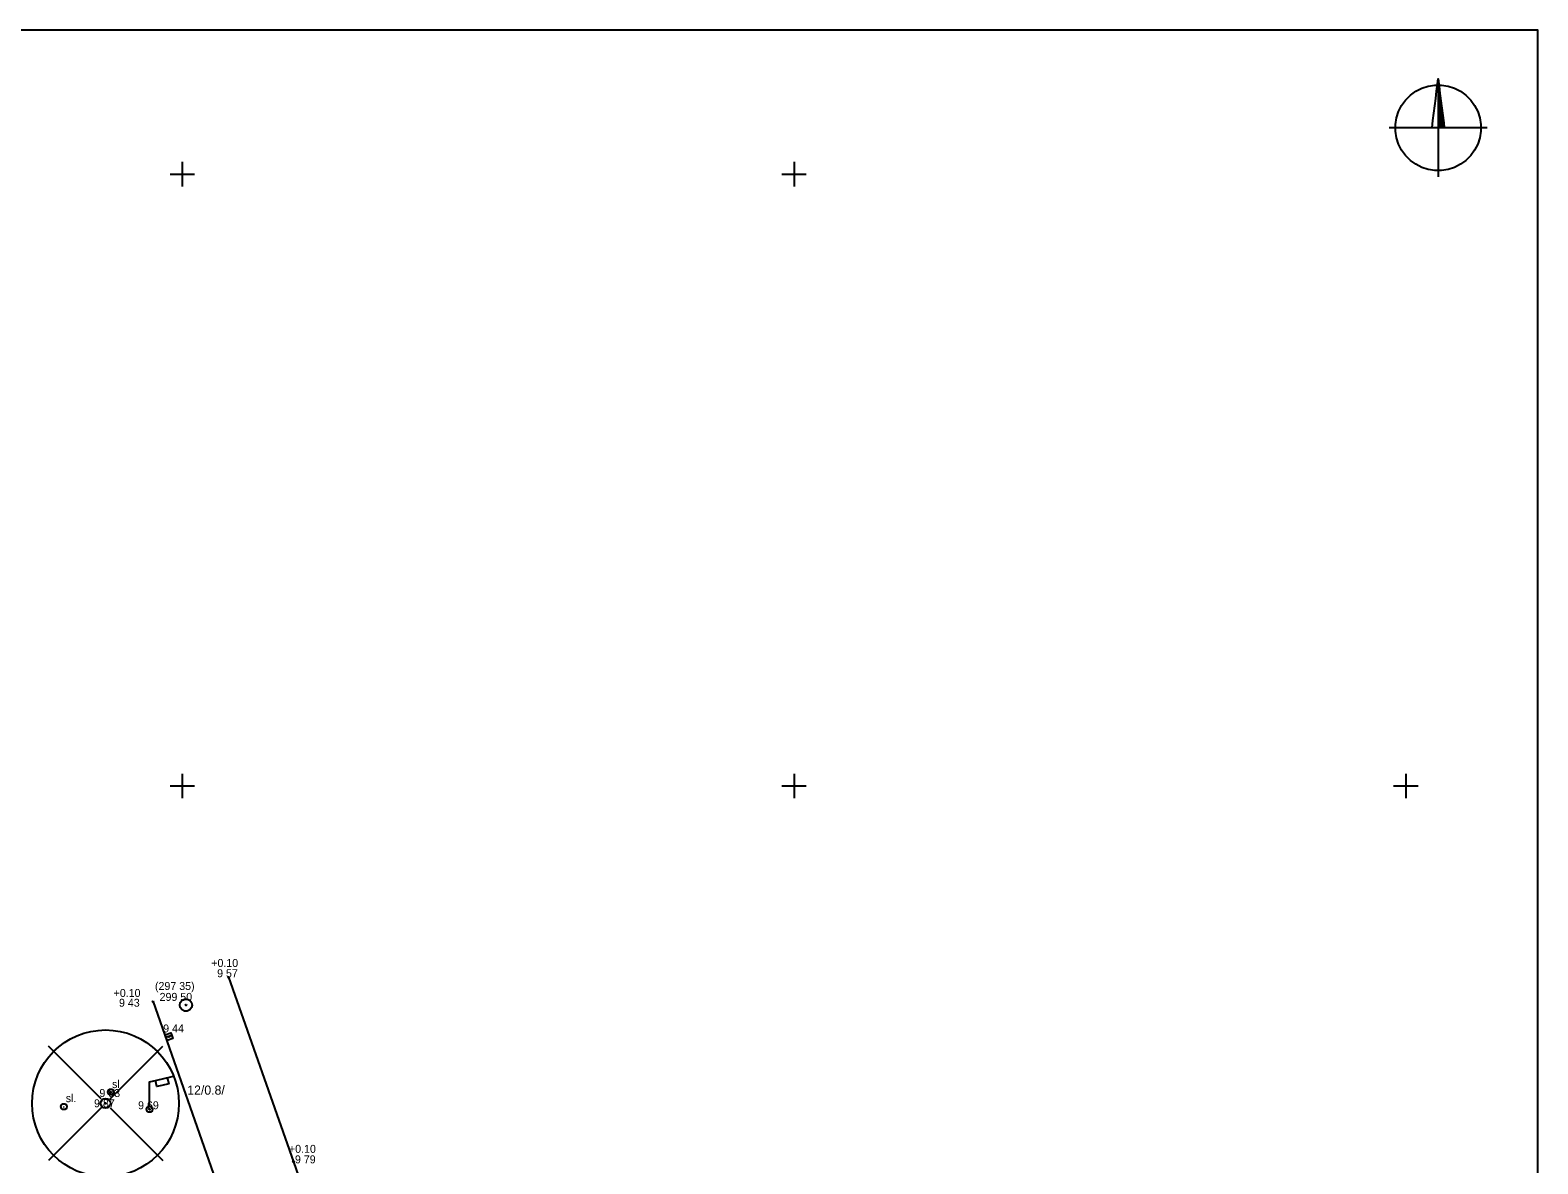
# Model space of a CAD drawing. Extents: x -684336 to -684039, y -993109 to -992688.
# Drawn here: x -684162.4 to -684039.2, y -992780.9 to -992688.2 of the extents above; entities that cross this region are included whole.
import ezdxf

# ---------------------------------------------------------------- set-up
doc = ezdxf.new("R2010")
doc.units = 0
for name, color, linetype in [('51', 7, 'Continuous'), ('53', 7, 'Continuous'), ('55', 7, 'Continuous'), ('56', 7, 'Continuous'), ('57', 7, 'Continuous'), ('60', 7, 'Continuous')]:
    doc.layers.add(name, color=color, linetype=linetype)

msp = doc.modelspace()

# ---------------------------------------------------------------- linework, layer by layer
at = {"layer": '51'}
for points in [[(-684146.21, -992765.63), (-684140.91, -992780.71), (-684133.67, -992801.48), (-684127.41, -992819.38), (-684119.65, -992841.73), (-684114.27, -992857.16), (-684108.6, -992873.5), (-684101.11, -992894.94), (-684096.5, -992908.14), (-684094.17, -992914.77), (-684093.17, -992916.04), (-684091.3, -992916.97), (-684089.29, -992917.17), (-684087.35, -992916.85), (-684086.32, -992916.52), (-684078.35, -992912.36)], [(-684152.39, -992767.63), (-684146.89, -992783.27), (-684139.8, -992803.58), (-684132.92, -992823.35), (-684125.99, -992843.22), (-684120.41, -992859.24), (-684115.07, -992874.61), (-684107.12, -992897.43), (-684102.52, -992910.64)]]:
    msp.add_lwpolyline(points, dxfattribs=at)
at = {"layer": '53'}
for points in [[(-684336.21, -993108.73), (-684039.21, -993108.73), (-684039.21, -992688.23), (-684336.21, -992688.23)], [(-684047.09, -992692.72), (-684046.55, -992692.8), (-684046.03, -992692.97), (-684045.54, -992693.22), (-684045.09, -992693.55), (-684044.7, -992693.94), (-684044.38, -992694.38), (-684044.13, -992694.87), (-684043.96, -992695.39), (-684043.87, -992695.93), (-684043.87, -992696.48), (-684043.96, -992697.02), (-684044.13, -992697.54), (-684044.38, -992698.03), (-684044.7, -992698.48), (-684045.09, -992698.87), (-684045.54, -992699.19), (-684046.03, -992699.44), (-684046.55, -992699.61), (-684047.09, -992699.7), (-684047.64, -992699.7), (-684048.18, -992699.61), (-684048.7, -992699.44), (-684049.19, -992699.19), (-684049.63, -992698.87), (-684050.02, -992698.48), (-684050.35, -992698.03), (-684050.6, -992697.54), (-684050.77, -992697.02), (-684050.85, -992696.48), (-684050.85, -992695.93), (-684050.77, -992695.39), (-684050.6, -992694.87), (-684050.35, -992694.38), (-684050.02, -992693.94), (-684049.63, -992693.55), (-684049.19, -992693.22), (-684048.7, -992692.97), (-684048.18, -992692.8), (-684047.64, -992692.72)]]:
    msp.add_lwpolyline(points, close=True, dxfattribs=at)
for points in [[(-684047.86, -992696.21), (-684047.79, -992695.61), (-684047.71, -992695.01), (-684047.64, -992694.41), (-684047.56, -992693.81), (-684047.49, -992693.21), (-684047.41, -992692.61), (-684047.36, -992692.21), (-684047.29, -992692.81), (-684047.21, -992693.41), (-684047.14, -992694.01), (-684047.06, -992694.61), (-684046.99, -992695.21), (-684046.91, -992695.81), (-684046.86, -992696.21), (-684046.9, -992696.17), (-684046.9, -992695.93), (-684046.94, -992695.61), (-684046.94, -992696.17), (-684046.98, -992696.17), (-684046.98, -992695.53), (-684046.98, -992695.29), (-684047.02, -992694.97), (-684047.02, -992695.6), (-684047.02, -992696.17), (-684047.06, -992696.17), (-684047.06, -992695.53), (-684047.06, -992694.9), (-684047.06, -992694.65), (-684047.1, -992694.37), (-684047.1, -992695), (-684047.1, -992695.64), (-684047.1, -992696.17), (-684047.14, -992696.17), (-684047.14, -992695.53), (-684047.14, -992694.9), (-684047.14, -992694.26), (-684047.14, -992694.05), (-684047.18, -992693.69), (-684047.18, -992694.32), (-684047.18, -992694.96), (-684047.18, -992695.59), (-684047.18, -992696.17), (-684047.22, -992696.17), (-684047.22, -992695.53), (-684047.22, -992694.9), (-684047.22, -992694.26), (-684047.22, -992693.63), (-684047.22, -992693.41), (-684047.26, -992693.05), (-684047.26, -992693.68), (-684047.26, -992694.32), (-684047.26, -992694.95), (-684047.26, -992695.59), (-684047.26, -992696.17), (-684047.3, -992696.17), (-684047.3, -992695.53), (-684047.3, -992694.9), (-684047.3, -992694.26), (-684047.3, -992693.63), (-684047.3, -992692.99), (-684047.3, -992692.73), (-684047.34, -992692.41), (-684047.34, -992693.04), (-684047.34, -992693.68), (-684047.34, -992694.31), (-684047.34, -992694.95), (-684047.34, -992695.58), (-684047.34, -992696.17)], [(-684047.36, -992692.21), (-684047.36, -992692.84), (-684047.36, -992693.48), (-684047.36, -992694.11), (-684047.36, -992694.75), (-684047.36, -992695.38), (-684047.36, -992696.02), (-684047.36, -992696.65), (-684047.36, -992697.29), (-684047.36, -992697.92), (-684047.36, -992698.56), (-684047.36, -992699.19), (-684047.36, -992699.83), (-684047.36, -992700.21)], [(-684043.36, -992696.21), (-684044, -992696.21), (-684044.63, -992696.21), (-684045.27, -992696.21), (-684045.9, -992696.21), (-684046.54, -992696.21), (-684047.17, -992696.21), (-684047.81, -992696.21), (-684048.44, -992696.21), (-684049.08, -992696.21), (-684049.71, -992696.21), (-684050.35, -992696.21), (-684050.98, -992696.21), (-684051.36, -992696.21)], [(-684150, -992699), (-684150, -992701)], [(-684100, -992699), (-684100, -992701)], [(-684151, -992700), (-684149, -992700)], [(-684101, -992700), (-684099, -992700)], [(-684150, -992749), (-684150, -992751)], [(-684100, -992749), (-684100, -992751)], [(-684050, -992749), (-684050, -992751)], [(-684151, -992750), (-684149, -992750)], [(-684101, -992750), (-684099, -992750)], [(-684051, -992750), (-684049, -992750)]]:
    msp.add_lwpolyline(points, dxfattribs=at)
at = {"layer": '55'}
for points in [[(-684149.59, -992767.42), (-684149.39, -992767.51), (-684149.25, -992767.69), (-684149.2, -992767.9), (-684149.25, -992768.11), (-684149.39, -992768.29), (-684149.59, -992768.39), (-684149.82, -992768.39), (-684150.01, -992768.29), (-684150.16, -992768.11), (-684150.2, -992767.9), (-684150.16, -992767.69), (-684150.01, -992767.51), (-684149.82, -992767.42)], [(-684155.75, -992774.78), (-684155.62, -992774.87), (-684155.58, -992775.02), (-684155.62, -992775.16), (-684155.75, -992775.25), (-684155.91, -992775.25), (-684156.03, -992775.16), (-684156.08, -992775.02), (-684156.03, -992774.87), (-684155.91, -992774.78)], [(-684159.59, -992775.97), (-684159.47, -992776.06), (-684159.42, -992776.2), (-684159.47, -992776.35), (-684159.59, -992776.44), (-684159.75, -992776.44), (-684159.87, -992776.35), (-684159.92, -992776.2), (-684159.87, -992776.06), (-684159.75, -992775.97)]]:
    msp.add_lwpolyline(points, close=True, dxfattribs=at)
for points in [[(-684150.85, -992770.4), (-684150.77, -992770.63), (-684151.24, -992770.8), (-684151.41, -992770.33), (-684150.94, -992770.16), (-684150.85, -992770.4), (-684151.33, -992770.56)], [(-684152.67, -992776.19), (-684152.59, -992776.19), (-684152.47, -992776.28), (-684152.42, -992776.42), (-684152.47, -992776.57), (-684152.59, -992776.66), (-684152.75, -992776.66), (-684152.87, -992776.57), (-684152.92, -992776.42), (-684152.87, -992776.28), (-684152.75, -992776.19), (-684152.67, -992776.19), (-684152.67, -992775.55), (-684152.67, -992774.92), (-684152.67, -992774.28), (-684152.67, -992774.17), (-684152.08, -992774.04), (-684151.5, -992773.9), (-684150.92, -992773.77), (-684150.72, -992773.72)], [(-684151.22, -992773.84), (-684151.09, -992774.34), (-684151.68, -992774.48), (-684152.07, -992774.57), (-684152.2, -992774.07)], [(-684155.85, -992775.02), (-684155.8, -992775.02)], [(-684159.7, -992776.21), (-684159.64, -992776.21)], [(-684152.7, -992776.42), (-684152.65, -992776.42)]]:
    msp.add_lwpolyline(points, dxfattribs=at)
at = {"layer": '57'}
for points in [[(-684146.19, -992765.59), (-684146.16, -992765.63), (-684146.19, -992765.67), (-684146.23, -992765.67), (-684146.26, -992765.63), (-684146.23, -992765.59)], [(-684152.37, -992767.59), (-684152.34, -992767.63), (-684152.37, -992767.67), (-684152.41, -992767.67), (-684152.44, -992767.63), (-684152.41, -992767.59)], [(-684149.68, -992767.86), (-684149.65, -992767.9), (-684149.68, -992767.94), (-684149.72, -992767.94), (-684149.74, -992767.9), (-684149.72, -992767.86)], [(-684151.07, -992770.44), (-684151.04, -992770.48), (-684151.07, -992770.52), (-684151.11, -992770.52), (-684151.14, -992770.48), (-684151.11, -992770.44)], [(-684155.81, -992774.98), (-684155.78, -992775.02), (-684155.81, -992775.06), (-684155.85, -992775.06), (-684155.88, -992775.02), (-684155.85, -992774.98)], [(-684156.25, -992775.9), (-684156.22, -992775.94), (-684156.25, -992775.98), (-684156.29, -992775.98), (-684156.32, -992775.94), (-684156.29, -992775.9)], [(-684152.65, -992776.38), (-684152.62, -992776.42), (-684152.65, -992776.46), (-684152.69, -992776.46), (-684152.72, -992776.42), (-684152.69, -992776.38)], [(-684140.89, -992780.67), (-684140.86, -992780.71), (-684140.89, -992780.75), (-684140.93, -992780.75), (-684140.96, -992780.71), (-684140.93, -992780.67)]]:
    msp.add_lwpolyline(points, close=True, dxfattribs=at)
at = {"layer": '60'}
for points in [[(-684156.64, -992775.57), (-684160.94, -992771.27)], [(-684155.9, -992775.57), (-684151.6, -992771.27)], [(-684156.64, -992776.31), (-684160.94, -992780.61)], [(-684155.9, -992776.31), (-684151.6, -992780.61)]]:
    msp.add_lwpolyline(points, dxfattribs=at)
for radius in [6, 0.4]:
    msp.add_circle((-684156.27, -992775.94), radius, dxfattribs=at)

# ---------------------------------------------------------------- texts
at = {"layer": '56'}
for p in [(-684155.74, -992774.69), (-684159.52, -992775.84)]:
    msp.add_text('sl.', height=0.65, dxfattribs=at).set_placement(p)
at = {"layer": '57'}
for s, p in [('+0.10', (-684147.63, -992764.79)), ('9 57', (-684147.15, -992765.63)), ('+0.10', (-684155.61, -992767.24)), ('(297 35)', (-684152.23, -992766.67)), ('9 43', (-684155.17, -992768.04)), ('299 50', (-684151.85, -992767.56)), ('9 44', (-684151.56, -992770.14)), ('9 93', (-684156.77, -992775.42)), ('9 87', (-684157.21, -992776.26)), ('9 69', (-684153.61, -992776.42)), ('+0.10', (-684141.28, -992779.98)), ('9 79', (-684140.79, -992780.84))]:
    msp.add_text(s, height=0.65, dxfattribs=at).set_placement(p)
at = {"layer": '60'}
msp.add_text('12/0.8/', height=0.75, dxfattribs=at).set_placement((-684149.59, -992775.23))

doc.saveas('drawing.dxf')
